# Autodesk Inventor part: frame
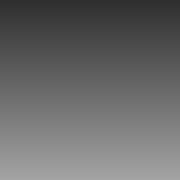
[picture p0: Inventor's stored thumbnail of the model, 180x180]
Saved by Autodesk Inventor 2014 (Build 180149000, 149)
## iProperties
Created: 2009-11
Part Number: frame
Document SubType Name: Modeling
Designer: pokornp
Density: 1 g/cm^3
Material: Generic
Appearance: Default
Author: pokornp
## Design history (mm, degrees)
sketch "Sketch1"
  geometry: L1 (300, 0)-(300, -1960); L2 (1200, 0)-(1200, -1960); L3 (300, -980)-(1200, -980); 1 further point
  constraints: 6 end point, 2 horizontal alignment, 2 midpoint
  dimensions: "w" = 1960 distance of L2.start L2.end; "d5" = 900 distance between parallel lines of L1 L2; "d7" = 980 distance from line of L2.end L3 (= 0.5 x w)
sketch "3D Sketch1"
